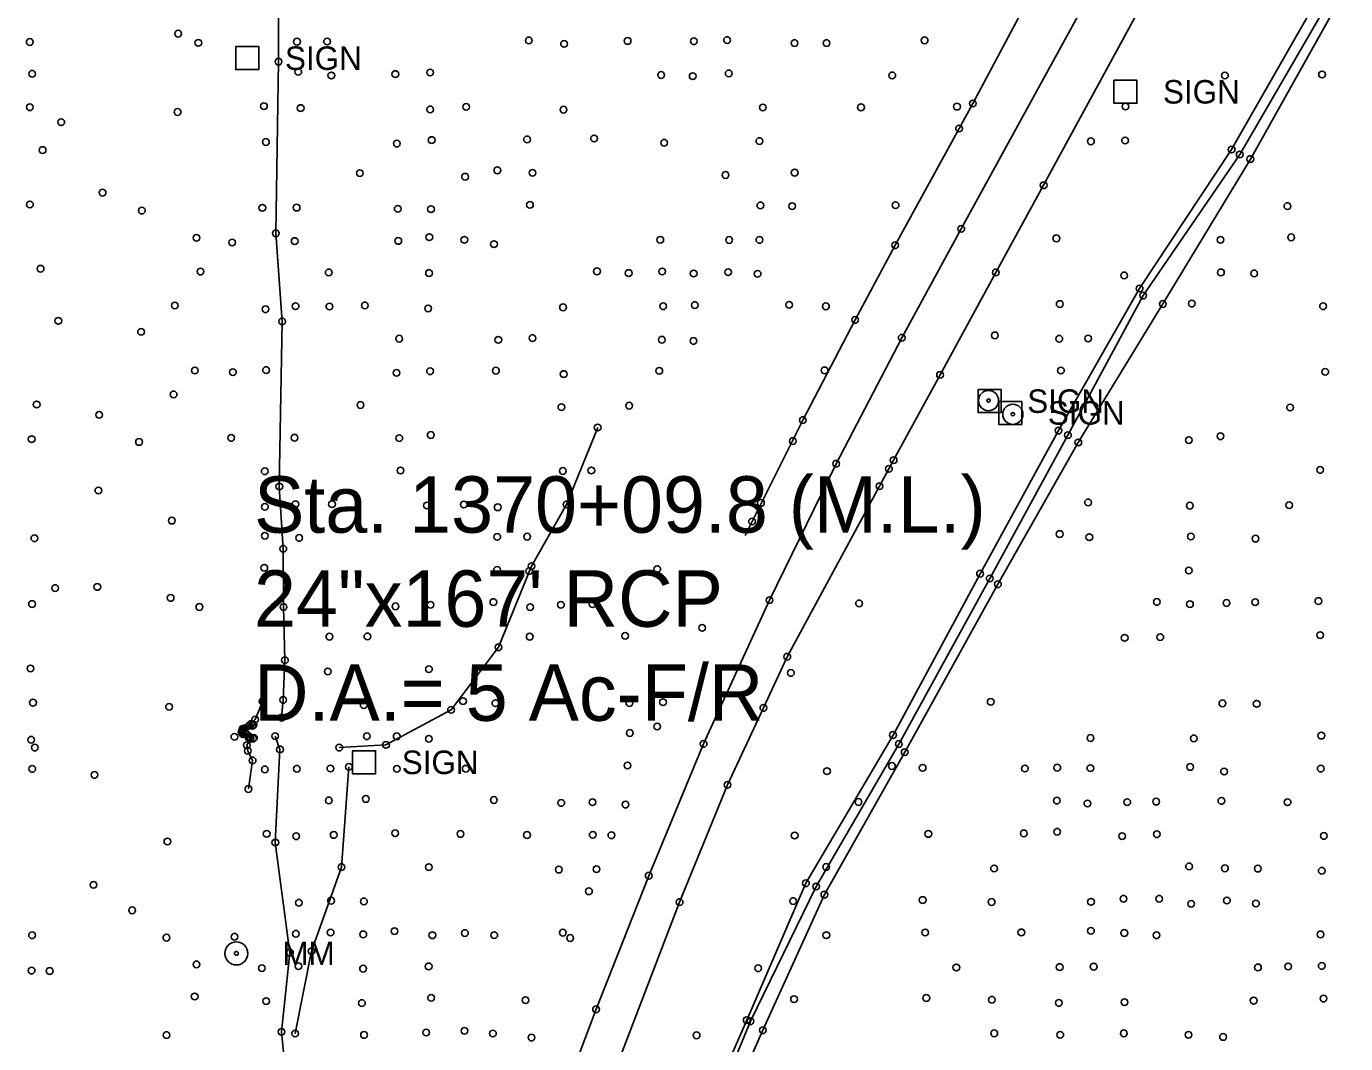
# Model space of a CAD drawing. Extents: x 20503438 to 20508873, y 7964251 to 7984667.
# Drawn here: x 20506685.7 to 20507078.6, y 7969717.3 to 7970020.1 of the extents above; entities that cross this region are included whole.
import ezdxf

# ---------------------------------------------------------------- set-up
doc = ezdxf.new("R2010")
doc.units = 0
for name, color, linetype in [('SurBreakLine', 7, 'Continuous'), ('SurConcreteSlab', 7, 'Continuous'), ('SurDrainageArrowDown', 7, 'Continuous'), ('SurDrainageArrowUp', 7, 'Continuous'), ('SurEdgeRoadPaved', 7, 'Continuous'), ('SurRoadPoints', 7, 'Continuous'), ('SurSurveyPoints', 7, 'Continuous'), ('SurTopOfWater', 7, 'Continuous'), ('SurTxtDrainage', 7, 'Continuous')]:
    doc.layers.add(name, color=color, linetype=linetype)

msp = doc.modelspace()

# ---------------------------------------------------------------- linework, layer by layer
at = {"layer": 'SurBreakLine'}
for points in [[(20507072.22, 7970031.81), (20507044.65, 7969983.45), (20507017.24, 7969942.09), (20506993.08, 7969899.77), (20506969.73, 7969857.18), (20506943.8, 7969809.14), (20506917.86, 7969765.01), (20506900.22, 7969724.24), (20506883.74, 7969686.63), (20506869.66, 7969642.53), (20506857.03, 7969597), (20506846.45, 7969549.54), (20506832.21, 7969502.12), (20506826.5, 7969481.38)], [(20507077.67, 7970029.62), (20507050.22, 7969980.63), (20507024.17, 7969937.47), (20506998.98, 7969896.23), (20506975.04, 7969854.03), (20506947.28, 7969804.04), (20506923.35, 7969761.61), (20506905.03, 7969721.23), (20506888.8, 7969684.78), (20506873.33, 7969642.22), (20506862.58, 7969597.47), (20506850.72, 7969549.13), (20506836.64, 7969499.73), (20506830.12, 7969478.04)], [(20506756.08, 7969819.19), (20506753.82, 7969813.74), (20506752.62, 7969812.45), (20506751.92, 7969811.89), (20506750.06, 7969810.95), (20506749.74, 7969809.97), (20506750.2, 7969809.4), (20506751.84, 7969808.39), (20506752.42, 7969808.08), (20506751.36, 7969806.11), (20506751.64, 7969804.43), (20506753.06, 7969801.59), (20506751.81, 7969793.07)], [(20506765.71, 7969720.27), (20506770.63, 7969744.77), (20506779.53, 7969769.82), (20506781.75, 7969799.68)]]:
    msp.add_lwpolyline(points, dxfattribs=at)
at = {"layer": 'SurConcreteSlab'}
for points in [[(20506786.98, 7969498.59), (20506791.56, 7969518.77), (20506801.71, 7969559.92), (20506813.33, 7969602.11), (20506824.94, 7969641.33), (20506838.85, 7969683.67), (20506855.36, 7969727.47), (20506871.04, 7969767.26), (20506887.39, 7969806.48), (20506907.03, 7969849.3), (20506926.87, 7969889.92), (20506946.4, 7969927.42), (20506964.13, 7969959.84), (20506998.31, 7970022.29), (20507028.85, 7970078.15), (20507050.93, 7970118.98), (20507063.43, 7970141.95), (20507094.89, 7970195.02), (20507112.55, 7970224.35), (20507146.84, 7970287.64), (20507180.2, 7970349.4), (20507227.5, 7970437.73), (20507263.67, 7970507.83), (20507275.78, 7970531.85)], [(20507015.79, 7970022.74), (20506988.66, 7969972.82), (20506974.4, 7969946.87), (20506957.8, 7969916.38), (20506943.98, 7969890.96), (20506942.58, 7969888.39), (20506939.78, 7969883.25), (20506912.31, 7969832.46), (20506905.2, 7969817.2), (20506894.52, 7969794.31), (20506880.24, 7969759.41), (20506853.16, 7969688.88), (20506840.87, 7969652.86), (20506836.17, 7969638.67), (20506828.63, 7969615.96), (20506819.26, 7969583.67), (20506809.41, 7969546.3), (20506800.9, 7969511.15), (20506797.61, 7969496.25), (20506795.23, 7969496.78)], [(20506753.29, 7969812.22), (20506750.75, 7969811.2), (20506750.19, 7969810.84), (20506750.03, 7969810.49), (20506750.04, 7969810.02), (20506750.35, 7969809.63), (20506752.08, 7969808.63), (20506753.25, 7969808.08)], [(20506753.29, 7969812.22), (20506753.04, 7969811.86), (20506750.79, 7969811.09), (20506750.2, 7969810.63), (20506750.2, 7969809.96), (20506751.32, 7969809.27), (20506753.46, 7969808.3), (20506753.25, 7969808.08)]]:
    msp.add_lwpolyline(points, dxfattribs=at)
at = {"layer": 'SurDrainageArrowDown'}
for points in [[(20506828.82, 7969479.38), (20506833.81, 7969500.36), (20506848.56, 7969549.36), (20506859.54, 7969596.56), (20506871.26, 7969642.69), (20506885.58, 7969685.72), (20506901.36, 7969723.92), (20506920.9, 7969764.04), (20506945.51, 7969806.46), (20506972.6, 7969855.74), (20506995.89, 7969898.43), (20507018.3, 7969939.97), (20507047.05, 7969981.99), (20507075.27, 7970030.65)], [(20506761.69, 7969645.23), (20506764.56, 7969691.5), (20506761.66, 7969720.78), (20506764.19, 7969744.34), (20506759.83, 7969777.16), (20506761.22, 7969804.86), (20506759.8, 7969808.78)]]:
    msp.add_lwpolyline(points, dxfattribs=at)
at = {"layer": 'SurDrainageArrowUp'}
for points in [[(20506761.71, 7969814.33), (20506762.15, 7969819.58), (20506762.7, 7969831.4), (20506762.26, 7969847.25), (20506762.2, 7969864.6), (20506761.02, 7969883.14), (20506761.89, 7969932.29), (20506759.98, 7969958.51), (20506760.78, 7970009.63), (20506760.9, 7970061.64), (20506759.44, 7970108.75), (20506759.6, 7970134.07), (20506759.96, 7970181.5), (20506762.42, 7970207.94), (20506763.22, 7970233.93), (20506762.99, 7970256.04), (20506763.79, 7970283.46), (20506764.08, 7970309.42), (20506762.66, 7970337.02), (20506760.9, 7970354.97)], [(20506778.87, 7969805.4), (20506792.79, 7969806.24), (20506812.18, 7969816.65), (20506826.28, 7969835.27), (20506836.15, 7969859.42), (20506846.55, 7969877.81), (20506855.84, 7969900.69)]]:
    msp.add_lwpolyline(points, dxfattribs=at)
at = {"layer": 'SurEdgeRoadPaved'}
msp.add_lwpolyline([(20506899.72, 7969868.51), (20506916.96, 7969902.91), (20506932.54, 7969932.73), (20506944.46, 7969954.96), (20506963.47, 7969989.72), (20506967.57, 7969997.18), (20506982.13, 7970024.6)], dxfattribs=at)
at = {"layer": 'SurRoadPoints'}
for points in [[(20506751.5, 7970007.24), (20506751.5, 7970007.24), (20506754.92, 7970007.24), (20506754.92, 7970014.09), (20506748.07, 7970014.09), (20506748.07, 7970007.24), (20506751.49, 7970007.24)], [(20507013, 7969997.22), (20507013, 7969997.22), (20507016.43, 7969997.22), (20507016.43, 7970004.08), (20507009.57, 7970004.08), (20507009.57, 7969997.22), (20507013, 7969997.22)], [(20506972.57, 7969905.12), (20506972.57, 7969905.12), (20506976, 7969905.12), (20506976, 7969911.98), (20506969.14, 7969911.98), (20506969.14, 7969905.12), (20506972.57, 7969905.12)], [(20506978.72, 7969901.62), (20506978.72, 7969901.62), (20506982.15, 7969901.62), (20506982.15, 7969908.48), (20506975.29, 7969908.48), (20506975.29, 7969901.62), (20506978.72, 7969901.62)], [(20506786.28, 7969797.58), (20506786.28, 7969797.58), (20506789.71, 7969797.58), (20506789.71, 7969804.44), (20506782.85, 7969804.44), (20506782.85, 7969797.58), (20506786.28, 7969797.58)]]:
    msp.add_lwpolyline(points, dxfattribs=at)
for centre, radius in [((20506972.25, 7969908.71), 3), ((20506972.25, 7969908.71), 0.5), ((20506979.48, 7969904.63), 3), ((20506979.48, 7969904.63), 0.5), ((20506748.23, 7969744.12), 3.43), ((20506748.23, 7969744.12), 0.571)]:
    msp.add_circle(centre, radius, dxfattribs=at)
at = {"layer": 'SurSurveyPoints'}
for centre in [(20506730.88, 7970017.95), (20506686.69, 7970015.48), (20506736.9, 7970015.24), (20506766.29, 7970015.58), (20506775.24, 7970015.61), (20506835.33, 7970015.95), (20506845.82, 7970014.91), (20506864.76, 7970015.78), (20506884.47, 7970015.69), (20506894.38, 7970016.05), (20506914.44, 7970015.16), (20506923.99, 7970015.16), (20506953.2, 7970015.97), (20506760.78, 7970009.63), (20506687.42, 7970006.03), (20506766.67, 7970006.6), (20506795.58, 7970005.93), (20506805.93, 7970006.38), (20506874.76, 7970005.65), (20506894.87, 7970006.12), (20506943.57, 7970005.53), (20507071.57, 7970005.8), (20506776.51, 7970005.5), (20506884.14, 7970005.3), (20507042.66, 7970005.52), (20506686.72, 7969996.04), (20506730.73, 7969994.63), (20506756.45, 7969996.35), (20506767.38, 7969995.8), (20506805.94, 7969995.4), (20506816.65, 7969996.16), (20506845.66, 7969995.32), (20506905.03, 7969995.99), (20506934.26, 7969996.02), (20506962.86, 7969996.23), (20506967.57, 7969997.18), (20507013.02, 7969996.27), (20506696.08, 7969991.6), (20506806.4, 7969986.27), (20506834.81, 7969986.47), (20506854.77, 7969986.74), (20506904.01, 7969985.97), (20506963.47, 7969989.72), (20507002.75, 7969985.9), (20507012.91, 7969986.14), (20506690.53, 7969983.31), (20506757.04, 7969985.7), (20506796, 7969985.22), (20506875.63, 7969985.48), (20507044.65, 7969983.45), (20507047.05, 7969981.99), (20507050.22, 7969980.63), (20506784.99, 7969976.44), (20506816.35, 7969975.37), (20506825.96, 7969977.26), (20506836.43, 7969976.54), (20506893.89, 7969975.87), (20506914.51, 7969976.57), (20506708.39, 7969970.62), (20506988.66, 7969972.82), (20506686.75, 7969967.09), (20506835.67, 7969967.01), (20506904.3, 7969966.83), (20506913.76, 7969966.59), (20506944.56, 7969966.89), (20507061.26, 7969966.63), (20506720.11, 7969965.27), (20506755.96, 7969966.12), (20506766.18, 7969966.16), (20506796.29, 7969965.82), (20506806.19, 7969965.7), (20506759.98, 7969958.51), (20506964.13, 7969959.84), (20506736.37, 7969957.16), (20506746.97, 7969955.76), (20506765.6, 7969956.21), (20506796.46, 7969956.25), (20506805.7, 7969957.37), (20506816.13, 7969956.59), (20506824.96, 7969955.28), (20506874.49, 7969956.59), (20506895.01, 7969956.53), (20506904, 7969956.55), (20506944.46, 7969954.96), (20506992.45, 7969957.02), (20507041.33, 7969956.58), (20507062.37, 7969957.31), (20506689.93, 7969947.98), (20506737.55, 7969947.11), (20506775.74, 7969946.88), (20506805.61, 7969946.68), (20506855.63, 7969947.19), (20506865.07, 7969946.69), (20506875.05, 7969947.16), (20506894.72, 7969946.95), (20506974.4, 7969946.87), (20507041.47, 7969946.87), (20506884.43, 7969946.54), (20506903.46, 7969946.47), (20507012.64, 7969945.99), (20507051.37, 7969946.58), (20507017.24, 7969942.09), (20507018.3, 7969939.97), (20506729.92, 7969937.04), (20506756.91, 7969935.9), (20506765.87, 7969936.82), (20506775.94, 7969936.71), (20506786.49, 7969937.05), (20506805.36, 7969936.14), (20506845.52, 7969936.47), (20506875.35, 7969936.79), (20506884.77, 7969937.15), (20506912.89, 7969937.22), (20506923.82, 7969936.77), (20506993.45, 7969937.46), (20507024.17, 7969937.47), (20507032.79, 7969937.59), (20507071.88, 7969936.8), (20506695.2, 7969932.46), (20506761.89, 7969932.29), (20506932.54, 7969932.73), (20506719.85, 7969929.2), (20506796.71, 7969927.14), (20506836.41, 7969927.33), (20506946.4, 7969927.42), (20506974.14, 7969928.13), (20506993.31, 7969927.12), (20507001.9, 7969927.2), (20506826.25, 7969926.82), (20506874.93, 7969926.84), (20506884.39, 7969926.47), (20506735.87, 7969917.69), (20506747.21, 7969917.18), (20506757.07, 7969917.79), (20506795.93, 7969916.96), (20506805.92, 7969917.44), (20506825.54, 7969917.62), (20506845.71, 7969916.6), (20506874.19, 7969917.57), (20506923.42, 7969917.71), (20506957.8, 7969916.38), (20506993.81, 7969917.66), (20507072.53, 7969917.29), (20506688.75, 7969907.56), (20506729.53, 7969910.56), (20506785.22, 7969907.39), (20506707.35, 7969904.46), (20506845.03, 7969906.75), (20506865.22, 7969907.2), (20507062.05, 7969906.64), (20506855.84, 7969900.69), (20506916.96, 7969902.91), (20506993.08, 7969899.77), (20506687.27, 7969897.23), (20506719.24, 7969896.39), (20506746.68, 7969897.6), (20506765.54, 7969897.66), (20506796.75, 7969897.54), (20506806.12, 7969898.47), (20506913.98, 7969896.67), (20506995.89, 7969898.43), (20506998.98, 7969896.23), (20507031.91, 7969896.92), (20507041.32, 7969898.09), (20506756.68, 7969887.67), (20506797.12, 7969887.9), (20506845.44, 7969887.74), (20506853.95, 7969887.89), (20506926.87, 7969889.92), (20506942.58, 7969888.39), (20506943.98, 7969890.96), (20507071.02, 7969888.06), (20506707.14, 7969881.95), (20506761.02, 7969883.14), (20506939.78, 7969883.25), (20506756.73, 7969877.08), (20506765.81, 7969877.88), (20506776.71, 7969877.86), (20506805, 7969877.46), (20506815.97, 7969877.77), (20506826.06, 7969876.94), (20506846.55, 7969877.81), (20506904.47, 7969878.23), (20507001.89, 7969878.4), (20507032.19, 7969877.42), (20507061.8, 7969877.56), (20506728.99, 7969872.97), (20506901.82, 7969872.7), (20506756.7, 7969868.46), (20506825.94, 7969868.13), (20506834.83, 7969868.2), (20506993.43, 7969868.98), (20507002.27, 7969868.04), (20507032.53, 7969868.26), (20506688.07, 7969867.72), (20506762.2, 7969864.6), (20506766.92, 7969867.82), (20507051.74, 7969867.61), (20506756.55, 7969858.92), (20506825.88, 7969858.3), (20506835.44, 7969857.95), (20506836.15, 7969859.42), (20506873.59, 7969858.53), (20506969.73, 7969857.18), (20507031.88, 7969858.13), (20506694.25, 7969852.9), (20506706.82, 7969853.23), (20506972.6, 7969855.74), (20506975.04, 7969854.03), (20506728.65, 7969849.96), (20506824.77, 7969848.73), (20506907.03, 7969849.3), (20507022.35, 7969848.77), (20507043.12, 7969848.44), (20507051.64, 7969848.68), (20507070.49, 7969849.03), (20506687.38, 7969848.14), (20506737.21, 7969847.26), (20506762.26, 7969847.25), (20506795.61, 7969847.45), (20506806.03, 7969847.92), (20506835.75, 7969847.22), (20506844.89, 7969847.91), (20506854.33, 7969848.1), (20506933.68, 7969848.33), (20507032.24, 7969848.12), (20506886.97, 7969841.06), (20506775.93, 7969838.43), (20506787.25, 7969838.5), (20506835.59, 7969838.43), (20506864.03, 7969838.68), (20507012.79, 7969838.08), (20507023.39, 7969838.29), (20507071.02, 7969838.89), (20506826.28, 7969835.27), (20506686.92, 7969828.96), (20506762.7, 7969831.4), (20506805.58, 7969828.73), (20506912.31, 7969832.46), (20506775.45, 7969828.07), (20506913.4, 7969827.62), (20506687.66, 7969818.78), (20506728.18, 7969817.55), (20506756.01, 7969819.17), (20506756.08, 7969819.19), (20506762.15, 7969819.58), (20506786.16, 7969818.02), (20506815.72, 7969819.23), (20506825.38, 7969818.63), (20506865.29, 7969818.68), (20506875.29, 7969818.92), (20506905.2, 7969817.2), (20506972.89, 7969819), (20507041.9, 7969818.58), (20507052.1, 7969818.42), (20506753.82, 7969813.74), (20506761.71, 7969814.33), (20506812.18, 7969816.65), (20506749.74, 7969809.97), (20506750.03, 7969810.49), (20506750.04, 7969810.02), (20506750.06, 7969810.95), (20506750.19, 7969810.84), (20506750.2, 7969810.63), (20506750.2, 7969809.96), (20506750.2, 7969809.4), (20506750.35, 7969809.63), (20506750.75, 7969811.2), (20506750.79, 7969811.09), (20506751.32, 7969809.27), (20506751.92, 7969811.89), (20506752.62, 7969812.45), (20506753.04, 7969811.86), (20506753.29, 7969812.22), (20506865.41, 7969809.74), (20506873.56, 7969811.68), (20506943.8, 7969809.14), (20506687.11, 7969807.74), (20506688.19, 7969805.4), (20506747.64, 7969808.61), (20506751.36, 7969806.11), (20506751.84, 7969808.39), (20506752.08, 7969808.63), (20506752.42, 7969808.08), (20506753.25, 7969808.08), (20506753.46, 7969808.3), (20506759.8, 7969808.78), (20506778.87, 7969805.4), (20506787.09, 7969808.77), (20506792.79, 7969806.24), (20506795.99, 7969808.75), (20506805.55, 7969808.02), (20506887.39, 7969806.48), (20506945.51, 7969806.46), (20507002.62, 7969808.25), (20507033.41, 7969808.13), (20507071.36, 7969808.96), (20506751.64, 7969804.43), (20506753.06, 7969801.59), (20506761.22, 7969804.86), (20506947.28, 7969804.04), (20506687.44, 7969799.05), (20506756.71, 7969798.9), (20506766.23, 7969799.1), (20506776.24, 7969799.19), (20506781.75, 7969799.68), (20506796.03, 7969799.09), (20506816.53, 7969799.1), (20506864.7, 7969800.07), (20506924.13, 7969798.37), (20506943.47, 7969799.91), (20506952.62, 7969799.37), (20506983.08, 7969799.18), (20506992.71, 7969799.42), (20507002.58, 7969799.28), (20507032.3, 7969799.63), (20507042.4, 7969798.27), (20507071.18, 7969799.14), (20506705.96, 7969797.26), (20506894.52, 7969794.31), (20506751.81, 7969793.07), (20506775.77, 7969789.67), (20506786.77, 7969790.1), (20506824.9, 7969789.8), (20506992.58, 7969789.62), (20507041.6, 7969789.51), (20506845, 7969788.92), (20506854.31, 7969789.14), (20506864.14, 7969788.43), (20506933.53, 7969789.2), (20507001.69, 7969788.77), (20507013.56, 7969789.17), (20507022.19, 7969789.31), (20507061.31, 7969789.13), (20506757.26, 7969779.72), (20506766.06, 7969779), (20506777.22, 7969779.39), (20506795.54, 7969779.9), (20506814.97, 7969779.68), (20506834.79, 7969779.37), (20506854.37, 7969779.43), (20506859.93, 7969779.3), (20506914.51, 7969779.21), (20506954.31, 7969779.69), (20506982.75, 7969779.86), (20506992.68, 7969780.34), (20507012.04, 7969779.03), (20507022.36, 7969779.59), (20507072.09, 7969779.09), (20506727.68, 7969777.44), (20506759.83, 7969777.16), (20506779.53, 7969769.82), (20506805.57, 7969769.81), (20506923.89, 7969769.85), (20507031.97, 7969770.02), (20506844.27, 7969769.06), (20506855.47, 7969769.19), (20506871.04, 7969767.26), (20506973.9, 7969769.42), (20507042.65, 7969769.45), (20507052.47, 7969769.36), (20507071.48, 7969768.74), (20506705.7, 7969764.53), (20506853.23, 7969762.61), (20506917.86, 7969765.01), (20506920.9, 7969764.04), (20506766.84, 7969759.2), (20506776.44, 7969759.82), (20506786.22, 7969759.61), (20506880.24, 7969759.41), (20506914.06, 7969759.7), (20506923.35, 7969761.61), (20506952.63, 7969760.01), (20506973.16, 7969759.43), (20507002.77, 7969759.47), (20507012.44, 7969760.39), (20507023.07, 7969760.4), (20507032.58, 7969758.86), (20507043.25, 7969759.87), (20507051.89, 7969758.97), (20506717.2, 7969756.94), (20506776.29, 7969750.33), (20506795.32, 7969750.75), (20506816.3, 7969750.17), (20506845.46, 7969750.3), (20506953.38, 7969750.36), (20506982.01, 7969750.38), (20507002.75, 7969750.84), (20507012.69, 7969750.19), (20506687.38, 7969749.52), (20506727.39, 7969748.8), (20506747.69, 7969749.08), (20506765.92, 7969749.97), (20506786.03, 7969749.79), (20506806.6, 7969749.52), (20506825.04, 7969749.57), (20506847.65, 7969748.7), (20506923.94, 7969749.54), (20507022.27, 7969749.52), (20507071.1, 7969749.79), (20506764.19, 7969744.34), (20506770.63, 7969744.77), (20506687.24, 7969739), (20506692.63, 7969738.88), (20506736.37, 7969740.84), (20506755.83, 7969739.74), (20506766.75, 7969740.31), (20506785.96, 7969739.58), (20506805.5, 7969740.25), (20506903.65, 7969739.7), (20506962.65, 7969739.93), (20506993.43, 7969740.05), (20507003.56, 7969740.17), (20507052.49, 7969739.95), (20507061.48, 7969740.24), (20507071.48, 7969740.39), (20506735.81, 7969731.31), (20506806.21, 7969730.91), (20506953.72, 7969730.84), (20507071.99, 7969730.67), (20506757.1, 7969729.91), (20506785.63, 7969729.33), (20506834.36, 7969730.2), (20506855.36, 7969727.47), (20506914.32, 7969730.49), (20506973.25, 7969730.33), (20506993.17, 7969729.37), (20507012.75, 7969729.61), (20507051.21, 7969730.05), (20506900.22, 7969724.24), (20506901.36, 7969723.92), (20506727.42, 7969719.81), (20506761.66, 7969720.78), (20506765.71, 7969720.27), (20506786.25, 7969719.85), (20506804.77, 7969720.56), (20506816.18, 7969721.08), (20506824.64, 7969720.29), (20506836.15, 7969719.05), (20506885.3, 7969719.73), (20506905.03, 7969721.23), (20506973.95, 7969720.32), (20506993.61, 7969719.87), (20507012.55, 7969720.32), (20507031.81, 7969719.87), (20507042.1, 7969719.24)]:
    msp.add_circle(centre, 1, dxfattribs=at)
at = {"layer": 'SurTopOfWater'}
for points in [[(20506751.88, 7969808.72), (20506751.92, 7969808.72), (20506751.92, 7969808.76), (20506751.88, 7969808.76)], [(20506751.9, 7969808.77), (20506751.9, 7969808.77), (20506751.9, 7969808.73), (20506751.9, 7969808.73)], [(20506751.9, 7969808.77), (20506751.9, 7969808.77), (20506751.9, 7969808.75), (20506751.9, 7969808.75)], [(20506751.9, 7969808.75), (20506751.9, 7969808.75), (20506751.9, 7969808.74), (20506751.9, 7969808.74)], [(20506751.9, 7969808.74), (20506751.9, 7969808.74), (20506751.9, 7969808.73), (20506751.9, 7969808.73)]]:
    msp.add_lwpolyline(points, close=True, dxfattribs=at)
for centre in [(20506751.89, 7969808.74), (20506751.9, 7969808.74), (20506751.91, 7969808.74)]:
    msp.add_arc(centre, 0.00586, 186.3566, 5.6839, dxfattribs=at)

# ---------------------------------------------------------------- texts
at = {"layer": 'SurRoadPoints'}
for s, p in [('SIGN', (20506762.71, 7970007.16)), ('SIGN', (20507024.21, 7969997.15)), ('SIGN', (20506983.78, 7969905.05)), ('SIGN', (20506989.93, 7969901.55)), ('SIGN', (20506797.49, 7969797.51)), ('MM', (20506761.94, 7969740.62))]:
    msp.add_text(s, height=6.995, rotation=360, dxfattribs=at).set_placement(p)
at = {"layer": 'SurTxtDrainage'}
for s, p in [('Sta. 1370+09.8 (M.L.)', (20506753.49, 7969869.37)), ('24"x167\' RCP', (20506753.49, 7969841.37)), ('D.A.= 5 Ac-F/R', (20506753.49, 7969813.37))]:
    msp.add_text(s, height=16.8, dxfattribs=at).set_placement(p)

doc.saveas('drawing.dxf')
